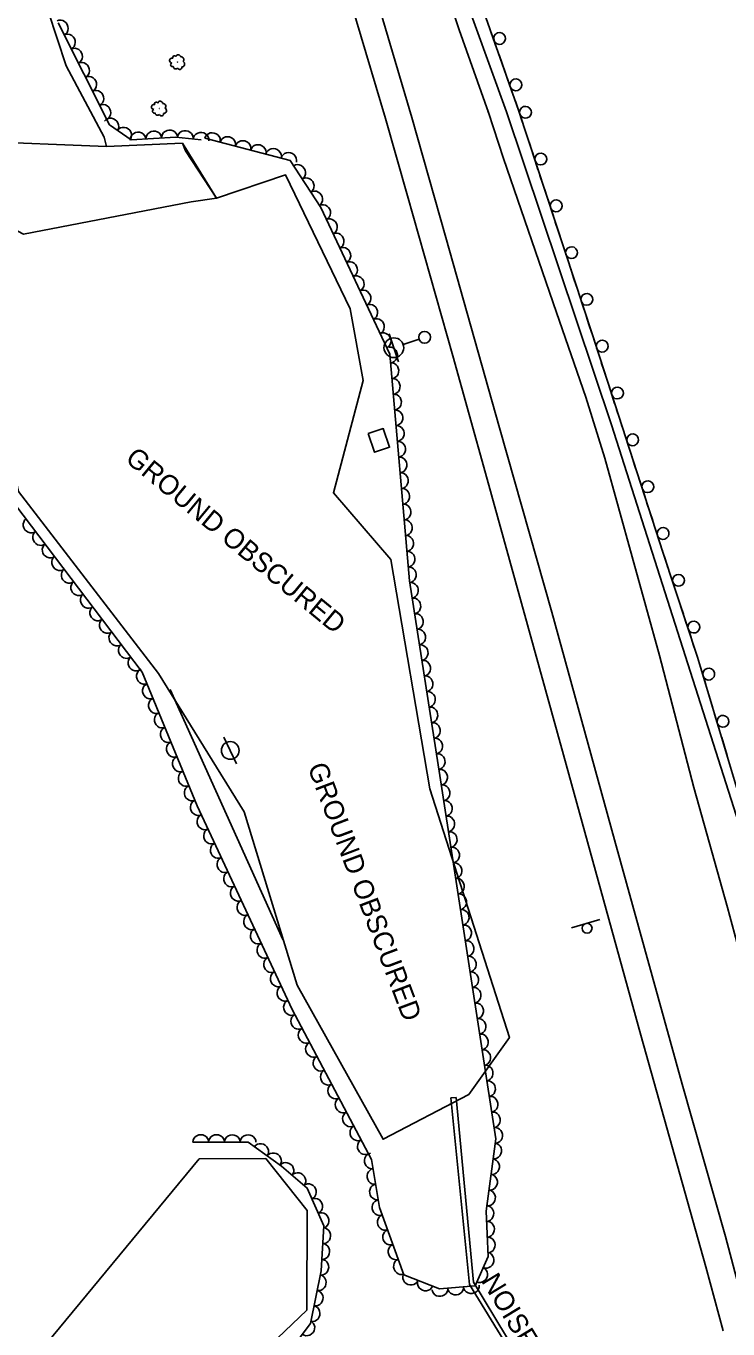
# Model space of a CAD drawing. Extents: x 1722896 to 1754269, y 648279 to 666297.
# Drawn here: x 1725650.9 to 1725829, y 657489.4 to 657820.2 of the extents above; entities that cross this region are included whole.
import ezdxf

# ---------------------------------------------------------------- set-up
doc = ezdxf.new("R2010")
doc.units = 0
for name, color, linetype in [('DESIGN - PUBLIC HEARING - Shapes', 7, 'Continuous'), ('DESIGN - SCRATCH - User 1', 7, 'Continuous'), ('SURVEY - CENTERLINE - Preliminary', 7, 'Continuous'), ('SURVEY - CENTERLINE - Preliminary Text', 7, 'Continuous'), ('SURVEY - DRAINAGE - Natural Features', 7, 'Continuous'), ('SURVEY - DTM - Breaklines', 7, 'Continuous'), ('SURVEY - VEGETATION - Features with Text', 7, 'Continuous')]:
    doc.layers.add(name, color=color, linetype=linetype)

msp = doc.modelspace()

# ---------------------------------------------------------------- linework, layer by layer
at = {"layer": 'DESIGN - PUBLIC HEARING - Shapes'}
msp.add_line((1725789.26, 657591.22), (1725796.45, 657593.37), dxfattribs=at)
msp.add_circle((1725793.23, 657591.13), 1.25, dxfattribs=at)
at = {"layer": 'DESIGN - SCRATCH - User 1'}
for points in [[(1725775.82, 657798.85), (1725766.57, 657825.21), (1725753.58, 657863.22), (1725740.47, 657907.21), (1725732.38, 657936.83), (1725723.98, 657969.44), (1725714.75, 658002.2), (1725707.1, 658034.27), (1725698.41, 658067.97), (1725690.34, 658103), (1725680.5, 658148.3), (1725676.61, 658172.79), (1725675.73, 658194.1)], [(1725770.37, 657814.38), (1725768.85, 657818.72)], [(1725771.68, 657810.65), (1725770.9, 657812.87)], [(1725772.46, 657808.43), (1725771.68, 657810.65)], [(1725774.51, 657802.58), (1725772.99, 657806.92)], [(1725775.82, 657798.85), (1725775.04, 657801.07)], [(1725856.32, 657541.35), (1725835.48, 657612.55), (1725821.24, 657659.92), (1725812.55, 657686.37), (1725794.57, 657741.74), (1725775.82, 657798.85)], [(1725776.87, 657795.65), (1725775.82, 657798.85)], [(1725778.11, 657791.9), (1725777.37, 657794.13)], [(1725778.84, 657789.67), (1725778.11, 657791.9)], [(1725780.77, 657783.77), (1725779.34, 657788.15)], [(1725782.01, 657780.02), (1725781.27, 657782.25)], [(1725782.74, 657777.79), (1725782.01, 657780.02)], [(1725784.67, 657771.9), (1725783.24, 657776.27)], [(1725785.9, 657768.15), (1725785.17, 657770.38)], [(1725786.64, 657765.91), (1725785.9, 657768.15)], [(1725788.57, 657760.02), (1725787.14, 657764.39)], [(1725789.8, 657756.27), (1725789.07, 657758.5)], [(1725790.54, 657754.04), (1725789.8, 657756.27)], [(1725792.47, 657748.15), (1725791.04, 657752.52)], [(1725793.7, 657744.39), (1725792.97, 657746.62)], [(1725794.44, 657742.16), (1725793.7, 657744.39)], [(1725796.35, 657736.26), (1725794.93, 657740.64)], [(1725797.57, 657732.51), (1725796.84, 657734.74)], [(1725798.3, 657730.27), (1725797.57, 657732.51)], [(1725800.21, 657724.37), (1725798.79, 657728.75)], [(1725801.43, 657720.62), (1725800.7, 657722.85)], [(1725802.16, 657718.38), (1725801.43, 657720.62)], [(1725804.07, 657712.48), (1725802.65, 657716.86)], [(1725805.29, 657708.73), (1725804.56, 657710.96)], [(1725806.01, 657706.49), (1725805.29, 657708.73)], [(1725807.93, 657700.59), (1725806.51, 657704.97)], [(1725809.15, 657696.84), (1725808.42, 657699.07)], [(1725809.87, 657694.6), (1725809.15, 657696.84)], [(1725811.79, 657688.7), (1725810.37, 657693.08)], [(1725813.01, 657684.95), (1725812.55, 657686.37), (1725812.28, 657687.18)], [(1725813.75, 657682.72), (1725813.01, 657684.95)], [(1725815.68, 657676.83), (1725814.25, 657681.2)], [(1725816.92, 657673.08), (1725816.18, 657675.31)], [(1725817.65, 657670.84), (1725816.92, 657673.08)], [(1725819.59, 657664.95), (1725818.15, 657669.32)], [(1725820.82, 657661.2), (1725820.09, 657663.43)], [(1725821.53, 657658.96), (1725821.24, 657659.92), (1725820.82, 657661.2)], [(1725823.31, 657653.02), (1725821.99, 657657.43)], [(1725824.45, 657649.24), (1725823.77, 657651.49)], [(1725825.13, 657646.99), (1725824.45, 657649.24)], [(1725826.91, 657641.05), (1725825.59, 657645.46)], [(1725828.05, 657637.27), (1725827.37, 657639.52)], [(1725828.72, 657635.02), (1725828.05, 657637.27)], [(1725797.06, 657445.74), (1725763.43, 657500.7), (1725758.67, 657548.05), (1725759.98, 657548.12), (1725764.4, 657501.26), (1725797.92, 657445.76), (1725797.06, 657445.74)]]:
    msp.add_lwpolyline(points, dxfattribs=at)
for centre, start, end in [((1725771.03, 657817.02), 312.6109, 312.6011), ((1725775.17, 657805.23), 312.6109, 312.6011), ((1725777.59, 657798.28), 311.4356, 311.4258), ((1725781.49, 657786.41), 311.4356, 311.4258), ((1725785.39, 657774.53), 311.4356, 311.4258), ((1725789.29, 657762.65), 311.4356, 311.4258), ((1725793.18, 657750.78), 311.4356, 311.4258), ((1725797.07, 657738.89), 311.2441, 311.2342), ((1725800.93, 657727), 311.2441, 311.2342), ((1725804.79, 657715.11), 311.2441, 311.2342), ((1725808.65, 657703.22), 311.2441, 311.2342), ((1725812.51, 657691.33), 311.2441, 311.2342), ((1725816.4, 657679.46), 311.4581, 311.4483), ((1725820.3, 657667.58), 311.4581, 311.4483), ((1725824.09, 657655.64), 309.9853, 309.9755), ((1725827.69, 657643.66), 309.9853, 309.9755)]:
    msp.add_arc(centre, 1.5, start, end, dxfattribs=at)
at = {"layer": 'SURVEY - CENTERLINE - Preliminary'}
for points in [[(1725649.71, 657844.86), (1725661.12, 657810.04), (1725670.75, 657792), (1725671.3, 657789.63), (1725690.57, 657790.46), (1725699.26, 657776.48), (1725692.77, 657775.5), (1725650.25, 657767.3), (1725633.56, 657776.23), (1725629.28, 657790.85), (1725614.02, 657822.78)], [(1725691.39, 657788.48), (1725699.26, 657776.48), (1725716.75, 657782.38), (1725733.15, 657748.36), (1725736.46, 657730.16), (1725728.89, 657701.69), (1725743.47, 657684.78), (1725753.32, 657626.51), (1725773.51, 657563.43), (1725763.25, 657548.94), (1725741.46, 657537.57), (1725719.72, 657576.64), (1725706.28, 657620.66), (1725684.47, 657655.8), (1725648.99, 657701.99), (1725633.03, 657776.94), (1725629.28, 657790.85), (1725637.54, 657790.97), (1725671.3, 657789.63), (1725690.57, 657790.46), (1725691.39, 657788.48)], [(1725694.79, 657532.58), (1725711.72, 657532.67), (1725722.21, 657519.5), (1725722.12, 657494.15), (1725705.52, 657478.22), (1725685.6, 657468.91), (1725664.88, 657466.37), (1725650.94, 657479.48), (1725694.79, 657532.58)]]:
    msp.add_lwpolyline(points, dxfattribs=at)
at = {"layer": 'SURVEY - CENTERLINE - Preliminary Text'}
for points in [[(1725625.56, 658417.38), (1725630.74, 658387.71), (1725636.38, 658347.79), (1725643.07, 658305.76), (1725650.08, 658266.7), (1725656.07, 658234.36), (1725663.21, 658197.98), (1725669.9, 658164.66), (1725679.72, 658120.16), (1725686.93, 658088.09), (1725696, 658049.77), (1725706.04, 658009), (1725715.13, 657973.82), (1725722.9, 657944.47), (1725732.92, 657907.88), (1725742.51, 657875.41), (1725752.72, 657843.16), (1725760.81, 657819.17)], [(1725611.6, 658413.08), (1725617.49, 658371.69), (1725623.56, 658332.44), (1725631.7, 658283), (1725640.24, 658236.86), (1725650.69, 658182.89), (1725658.81, 658142.9), (1725666.8, 658106.55), (1725675.1, 658071.09), (1725682.86, 658038.13), (1725691.42, 658003.35), (1725699.87, 657971.43), (1725708.55, 657939.39), (1725717.35, 657907.56), (1725727.39, 657871.59), (1725739.63, 657827.91), (1725748.8, 657796.95)], [(1725601.26, 658410.93), (1725609.52, 658357.27), (1725618.33, 658304.64), (1725626.05, 658259.69), (1725634.36, 658215.08), (1725644.65, 658159.71), (1725648.23, 658142.26), (1725650.86, 658142.78), (1725653.85, 658135.3), (1725662.43, 658098.81), (1725668.85, 658070.4), (1725676.11, 658038.34), (1725684.89, 658002.95), (1725693.64, 657969.51), (1725702.95, 657935.55), (1725711.34, 657905.03), (1725719.02, 657877.62), (1725726.62, 657850.51), (1725734.75, 657821.39), (1725742.13, 657796.69)], [(1725760.68, 657831.8), (1725772.81, 657798.38)], [(1725760.81, 657819.17), (1725768.22, 657798.26)], [(1725768.22, 657798.26), (1725768.05, 657798.48)], [(1725878.2, 657481.6), (1725860.46, 657459.9), (1725860.44, 657467.2), (1725860.06, 657477.41), (1725859.24, 657483.66), (1725857.4, 657492.07), (1725852.72, 657509.72), (1725846.06, 657535.43), (1725837.72, 657563.37), (1725828.83, 657596.43), (1725820.3, 657626.87), (1725811.56, 657660.37), (1725797.69, 657710.48), (1725792.87, 657725.93), (1725785.47, 657747.41), (1725772.03, 657786.57), (1725768.22, 657798.26)], [(1725772.81, 657798.38), (1725799.39, 657718.94), (1725833.01, 657613.7), (1725856.2, 657533.49), (1725868.25, 657492.66), (1725867.92, 657489.48)], [(1725827.74, 657488.93), (1725823.33, 657505.17), (1725806.85, 657563.97), (1725787.24, 657635.14), (1725767.44, 657706.64), (1725759.14, 657736.41), (1725747.65, 657777.04), (1725742.13, 657796.69)], [(1725748.8, 657796.95), (1725757.38, 657766.52), (1725771, 657718.17), (1725784.31, 657671.35), (1725800.19, 657613.59), (1725817.32, 657551.58), (1725828.34, 657512.84), (1725832.27, 657498.15), (1725835.49, 657484.05), (1725837.19, 657472.34), (1725837.4, 657468.86)], [(1725716.02, 657588.28), (1725687.43, 657651.76)]]:
    msp.add_lwpolyline(points, dxfattribs=at)
at = {"layer": 'SURVEY - DRAINAGE - Natural Features'}
msp.add_line((1725740.43, 657714.97), (1725740.43, 657714.97), dxfattribs=at)
msp.add_lwpolyline([(1725737.73, 657716.7), (1725741.52, 657717.98), (1725743.13, 657713.25), (1725739.34, 657711.96), (1725737.73, 657716.7)], dxfattribs=at)
at = {"layer": 'SURVEY - DTM - Breaklines'}
for p, q in [((1725744.21, 657738.51), (1725743, 657742.06)), ((1725744.21, 657738.51), (1725745.41, 657734.95)), ((1725750.6, 657740.67), (1725746.58, 657739.31)), ((1725702.71, 657636.26), (1725701.08, 657639.64)), ((1725702.71, 657636.26), (1725704.33, 657632.88))]:
    msp.add_line(p, q, dxfattribs=at)
for centre, radius in [((1725752.02, 657741.15), 1.5), ((1725744.21, 657738.51), 2.5), ((1725702.71, 657636.26), 2.25)]:
    msp.add_circle(centre, radius, dxfattribs=at)
at = {"layer": 'SURVEY - VEGETATION - Features with Text'}
for points in [[(1725659.05, 657820.97), (1725672.09, 657795.1), (1725677.6, 657791.24), (1725688.9, 657791.98), (1725695.3, 657791.27)], [(1725696.26, 657791.69), (1725717.93, 657786.05), (1725725.67, 657774.07), (1725743.21, 657736.89), (1725748.16, 657679.35), (1725755.86, 657629.87), (1725770.05, 657537.64), (1725767.65, 657519.32), (1725768.15, 657507.79), (1725764.83, 657500.38), (1725755.78, 657499.54), (1725746.78, 657503.12), (1725740.58, 657520.2), (1725738.58, 657532.42), (1725718.39, 657570.48), (1725694.28, 657622.2), (1725680.38, 657656.17), (1725646.22, 657701.24), (1725631.76, 657768.75), (1725623.69, 657794.46)], [(1725693.23, 657536.82), (1725707.26, 657536.81), (1725715.71, 657530.73), (1725722.23, 657525.15), (1725726.44, 657515.54), (1725725.74, 657504.11), (1725723.09, 657490.8), (1725714.72, 657479.72)]]:
    msp.add_lwpolyline(points, dxfattribs=at)
for centre in [(1725689.31, 657811.02), (1725684.72, 657799.22)]:
    msp.add_circle(centre, 0.022, dxfattribs=at)
for centre, radius, start, end in [((1725687.95, 657811.41), 0.629, 70.1013, 263.521), ((1725688.54, 657812.21), 0.433, 30.0806, 208.8263), ((1725689.53, 657812.26), 0.631, 7.9645, 164.7534), ((1725690.21, 657811.63), 0.719, 317.0172, 94.5414), ((1725690.42, 657810.5), 0.714, 267.913, 63.7515), ((1725688.07, 657810.34), 0.479, 112.72, 290.0391), ((1725688.9, 657809.98), 0.679, 188.007, 314.8527), ((1725689.88, 657809.67), 0.527, 198.1659, 13.1662), ((1725684.94, 657800.46), 0.631, 7.9645, 164.7534), ((1725683.36, 657799.61), 0.629, 70.1013, 263.521), ((1725683.47, 657798.54), 0.479, 112.72, 290.0391), ((1725683.95, 657800.41), 0.433, 30.0806, 208.8263), ((1725684.31, 657798.19), 0.679, 188.007, 314.8527), ((1725685.29, 657797.87), 0.527, 198.1659, 13.1662), ((1725685.62, 657799.83), 0.719, 317.0172, 94.5414), ((1725685.83, 657798.7), 0.714, 267.913, 63.7515)]:
    msp.add_arc(centre, radius, start, end, dxfattribs=at)
for centre, major_axis in [((1725659.69, 657819.69), (0.9, -1.79)), ((1725661.49, 657816.12), (0.9, -1.79)), ((1725663.3, 657812.55), (0.9, -1.79)), ((1725665.1, 657808.98), (0.9, -1.79)), ((1725666.9, 657805.41), (0.9, -1.79)), ((1725668.7, 657801.84), (0.9, -1.79)), ((1725670.5, 657798.26), (0.9, -1.79)), ((1725672.47, 657794.84), (1.64, -1.15)), ((1725675.74, 657792.54), (1.64, -1.15)), ((1725679.33, 657791.35), (2, 0.13)), ((1725683.32, 657791.61), (2, 0.13)), ((1725687.31, 657791.87), (2, 0.13)), ((1725691.29, 657791.71), (1.99, -0.22)), ((1725695.27, 657791.28), (1.99, -0.22)), ((1725698.2, 657791.19), (1.94, -0.5)), ((1725702.07, 657790.18), (1.94, -0.5)), ((1725705.94, 657789.17), (1.94, -0.5)), ((1725709.81, 657788.16), (1.94, -0.5)), ((1725713.68, 657787.16), (1.94, -0.5)), ((1725717.55, 657786.15), (1.94, -0.5)), ((1725719.89, 657783.02), (1.09, -1.68)), ((1725722.06, 657779.66), (1.09, -1.68)), ((1725724.23, 657776.3), (1.09, -1.68)), ((1725726.24, 657772.85), (0.85, -1.81)), ((1725727.95, 657769.23), (0.85, -1.81)), ((1725729.66, 657765.62), (0.85, -1.81)), ((1725731.36, 657762), (0.85, -1.81)), ((1725733.07, 657758.38), (0.85, -1.81)), ((1725734.77, 657754.76), (0.85, -1.81)), ((1725736.48, 657751.15), (0.85, -1.81)), ((1725738.19, 657747.53), (0.85, -1.81)), ((1725739.89, 657743.91), (0.85, -1.81)), ((1725741.6, 657740.29), (0.85, -1.81)), ((1725743.23, 657736.65), (0.17, -1.99)), ((1725743.57, 657732.67), (0.17, -1.99)), ((1725743.91, 657728.68), (0.17, -1.99)), ((1725744.25, 657724.7), (0.17, -1.99)), ((1725744.6, 657720.71), (0.17, -1.99)), ((1725744.94, 657716.73), (0.17, -1.99)), ((1725745.28, 657712.74), (0.17, -1.99)), ((1725745.63, 657708.76), (0.17, -1.99)), ((1725745.97, 657704.77), (0.17, -1.99)), ((1725746.31, 657700.78), (0.17, -1.99)), ((1725746.65, 657696.8), (0.17, -1.99)), ((1725652.12, 657693.45), (-1.21, 1.59)), ((1725654.53, 657690.27), (-1.21, 1.59)), ((1725747, 657692.81), (0.17, -1.99)), ((1725656.95, 657687.08), (-1.21, 1.59)), ((1725747.34, 657688.83), (0.17, -1.99)), ((1725659.37, 657683.89), (-1.21, 1.59)), ((1725747.68, 657684.84), (0.17, -1.99)), ((1725661.78, 657680.7), (-1.21, 1.59)), ((1725748.03, 657680.86), (0.17, -1.99)), ((1725664.2, 657677.52), (-1.21, 1.59)), ((1725748.54, 657676.89), (0.31, -1.98)), ((1725666.62, 657674.33), (-1.21, 1.59)), ((1725669.03, 657671.14), (-1.21, 1.59)), ((1725749.15, 657672.94), (0.31, -1.98)), ((1725671.45, 657667.95), (-1.21, 1.59)), ((1725749.77, 657668.99), (0.31, -1.98)), ((1725673.86, 657664.77), (-1.21, 1.59)), ((1725750.39, 657665.04), (0.31, -1.98)), ((1725676.28, 657661.58), (-1.21, 1.59)), ((1725751, 657661.08), (0.31, -1.98)), ((1725678.7, 657658.39), (-1.21, 1.59)), ((1725751.62, 657657.13), (0.31, -1.98)), ((1725680.84, 657655.05), (-0.76, 1.85)), ((1725682.36, 657651.34), (-0.76, 1.85)), ((1725752.23, 657653.18), (0.31, -1.98)), ((1725683.87, 657647.64), (-0.76, 1.85)), ((1725752.85, 657649.23), (0.31, -1.98)), ((1725685.38, 657643.94), (-0.76, 1.85)), ((1725753.46, 657645.27), (0.31, -1.98)), ((1725754.08, 657641.32), (0.31, -1.98)), ((1725686.9, 657640.24), (-0.76, 1.85)), ((1725754.69, 657637.37), (0.31, -1.98)), ((1725688.41, 657636.54), (-0.76, 1.85)), ((1725689.93, 657632.83), (-0.76, 1.85)), ((1725755.31, 657633.42), (0.31, -1.98)), ((1725691.44, 657629.13), (-0.76, 1.85)), ((1725755.92, 657629.47), (0.3, -1.98)), ((1725692.96, 657625.43), (-0.76, 1.85)), ((1725756.53, 657625.51), (0.3, -1.98)), ((1725694.5, 657621.74), (-0.85, 1.81)), ((1725757.14, 657621.56), (0.3, -1.98)), ((1725696.19, 657618.11), (-0.85, 1.81)), ((1725757.75, 657617.61), (0.3, -1.98)), ((1725697.88, 657614.49), (-0.85, 1.81)), ((1725758.36, 657613.65), (0.3, -1.98)), ((1725699.57, 657610.86), (-0.85, 1.81)), ((1725758.97, 657609.7), (0.3, -1.98)), ((1725701.26, 657607.24), (-0.85, 1.81)), ((1725759.58, 657605.74), (0.3, -1.98)), ((1725702.95, 657603.61), (-0.85, 1.81)), ((1725760.18, 657601.79), (0.3, -1.98)), ((1725704.64, 657599.98), (-0.85, 1.81)), ((1725760.79, 657597.84), (0.3, -1.98)), ((1725706.33, 657596.36), (-0.85, 1.81)), ((1725761.4, 657593.88), (0.3, -1.98)), ((1725708.02, 657592.73), (-0.85, 1.81)), ((1725709.71, 657589.11), (-0.85, 1.81)), ((1725762.01, 657589.93), (0.3, -1.98)), ((1725711.4, 657585.48), (-0.85, 1.81)), ((1725762.62, 657585.98), (0.3, -1.98)), ((1725713.09, 657581.86), (-0.85, 1.81)), ((1725763.23, 657582.02), (0.3, -1.98)), ((1725714.78, 657578.23), (-0.85, 1.81)), ((1725763.83, 657578.07), (0.3, -1.98)), ((1725716.47, 657574.61), (-0.85, 1.81)), ((1725764.44, 657574.12), (0.3, -1.98)), ((1725718.16, 657570.98), (-0.85, 1.81)), ((1725765.05, 657570.16), (0.3, -1.98)), ((1725720.01, 657567.44), (-0.94, 1.77)), ((1725765.66, 657566.21), (0.3, -1.98)), ((1725721.88, 657563.9), (-0.94, 1.77)), ((1725766.27, 657562.26), (0.3, -1.98)), ((1725723.75, 657560.37), (-0.94, 1.77)), ((1725766.88, 657558.3), (0.3, -1.98)), ((1725725.63, 657556.83), (-0.94, 1.77)), ((1725767.48, 657554.35), (0.3, -1.98)), ((1725727.5, 657553.3), (-0.94, 1.77)), ((1725729.38, 657549.77), (-0.94, 1.77)), ((1725768.09, 657550.4), (0.3, -1.98)), ((1725731.25, 657546.23), (-0.94, 1.77)), ((1725768.7, 657546.44), (0.3, -1.98)), ((1725733.13, 657542.7), (-0.94, 1.77)), ((1725769.31, 657542.49), (0.3, -1.98)), ((1725735, 657539.17), (-0.94, 1.77)), ((1725769.92, 657538.54), (0.3, -1.98)), ((1725695.23, 657536.82), (2, 0)), ((1725699.23, 657536.82), (2, 0)), ((1725703.23, 657536.81), (2, 0)), ((1725707.23, 657536.81), (2, 0)), ((1725710.48, 657534.5), (1.62, -1.17)), ((1725736.88, 657535.63), (-0.94, 1.77)), ((1725769.65, 657534.57), (-0.26, -1.98)), ((1725713.73, 657532.16), (1.62, -1.17)), ((1725738.64, 657532.06), (-0.32, 1.97)), ((1725716.89, 657529.72), (1.52, -1.3)), ((1725739.29, 657528.11), (-0.32, 1.97)), ((1725769.13, 657530.61), (-0.26, -1.98)), ((1725719.93, 657527.12), (1.52, -1.3)), ((1725722.62, 657524.26), (0.8, -1.83)), ((1725768.61, 657526.64), (-0.26, -1.98)), ((1725739.93, 657524.17), (-0.32, 1.97)), ((1725768.09, 657522.67), (-0.26, -1.98)), ((1725724.22, 657520.59), (0.8, -1.83)), ((1725740.58, 657520.22), (-0.32, 1.97)), ((1725767.68, 657518.7), (0.09, -2)), ((1725725.83, 657516.93), (0.8, -1.83)), ((1725741.94, 657516.46), (-0.68, 1.88)), ((1725767.85, 657514.71), (0.09, -2)), ((1725726.29, 657513.06), (-0.12, -2)), ((1725743.3, 657512.7), (-0.68, 1.88)), ((1725726.04, 657509.07), (-0.12, -2)), ((1725744.67, 657508.94), (-0.68, 1.88)), ((1725768.02, 657510.71), (0.09, -2)), ((1725725.8, 657505.08), (-0.12, -2)), ((1725746.04, 657505.18), (-0.68, 1.88)), ((1725767.71, 657506.81), (-0.82, -1.82)), ((1725766.07, 657503.16), (-0.82, -1.82)), ((1725725.15, 657501.14), (-0.39, -1.96)), ((1725748.47, 657502.45), (-1.86, 0.74)), ((1725752.18, 657500.97), (-1.86, 0.74)), ((1725759.89, 657499.92), (-1.99, -0.19)), ((1725763.87, 657500.29), (-1.99, -0.19)), ((1725724.37, 657497.22), (-0.39, -1.96)), ((1725755.91, 657499.55), (-1.99, -0.19)), ((1725723.59, 657493.29), (-0.39, -1.96)), ((1725722.21, 657489.64), (-1.21, -1.6))]:
    msp.add_ellipse(centre, major_axis=major_axis, ratio=0.940188, start_param=0, end_param=3.141593, dxfattribs=at)

# ---------------------------------------------------------------- texts
at = {"layer": 'DESIGN - SCRATCH - User 1'}
msp.add_text('NOISE WALL', height=5, rotation=301.3109, dxfattribs=at).set_placement((1725766.26, 657501.6))
at = {"layer": 'SURVEY - CENTERLINE - Preliminary'}
for rotation, p in [(320.4582, (1725675.8, 657709.82)), (290.6805, (1725722.27, 657632.06))]:
    msp.add_text('GROUND OBSCURED', height=5, rotation=rotation, dxfattribs=at).set_placement(p)

doc.saveas('drawing.dxf')
